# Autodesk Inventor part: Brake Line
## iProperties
Shininess: 20.0
Angle Display Precision: 2
Document Length Units: 11269
Document Angle Units: 11279
Document Time Units: 11290
Document Mass Units: 11283
Document Length Units Precision: 3
Document Angle Units Precision: 2
Compacted: True
Created: 2001-09
Part Number: Brake Line
Document SubType Name: Modeling
Designer: Martin Budgell
Density: 0.0
Volumn: 0.0
Area: 0.0
PropertySet Name: Model Information
Control State: 0
Master: False
Checked Out: False
Author: Martin Budgell
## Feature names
1. Sweep1
2. Sweep2
